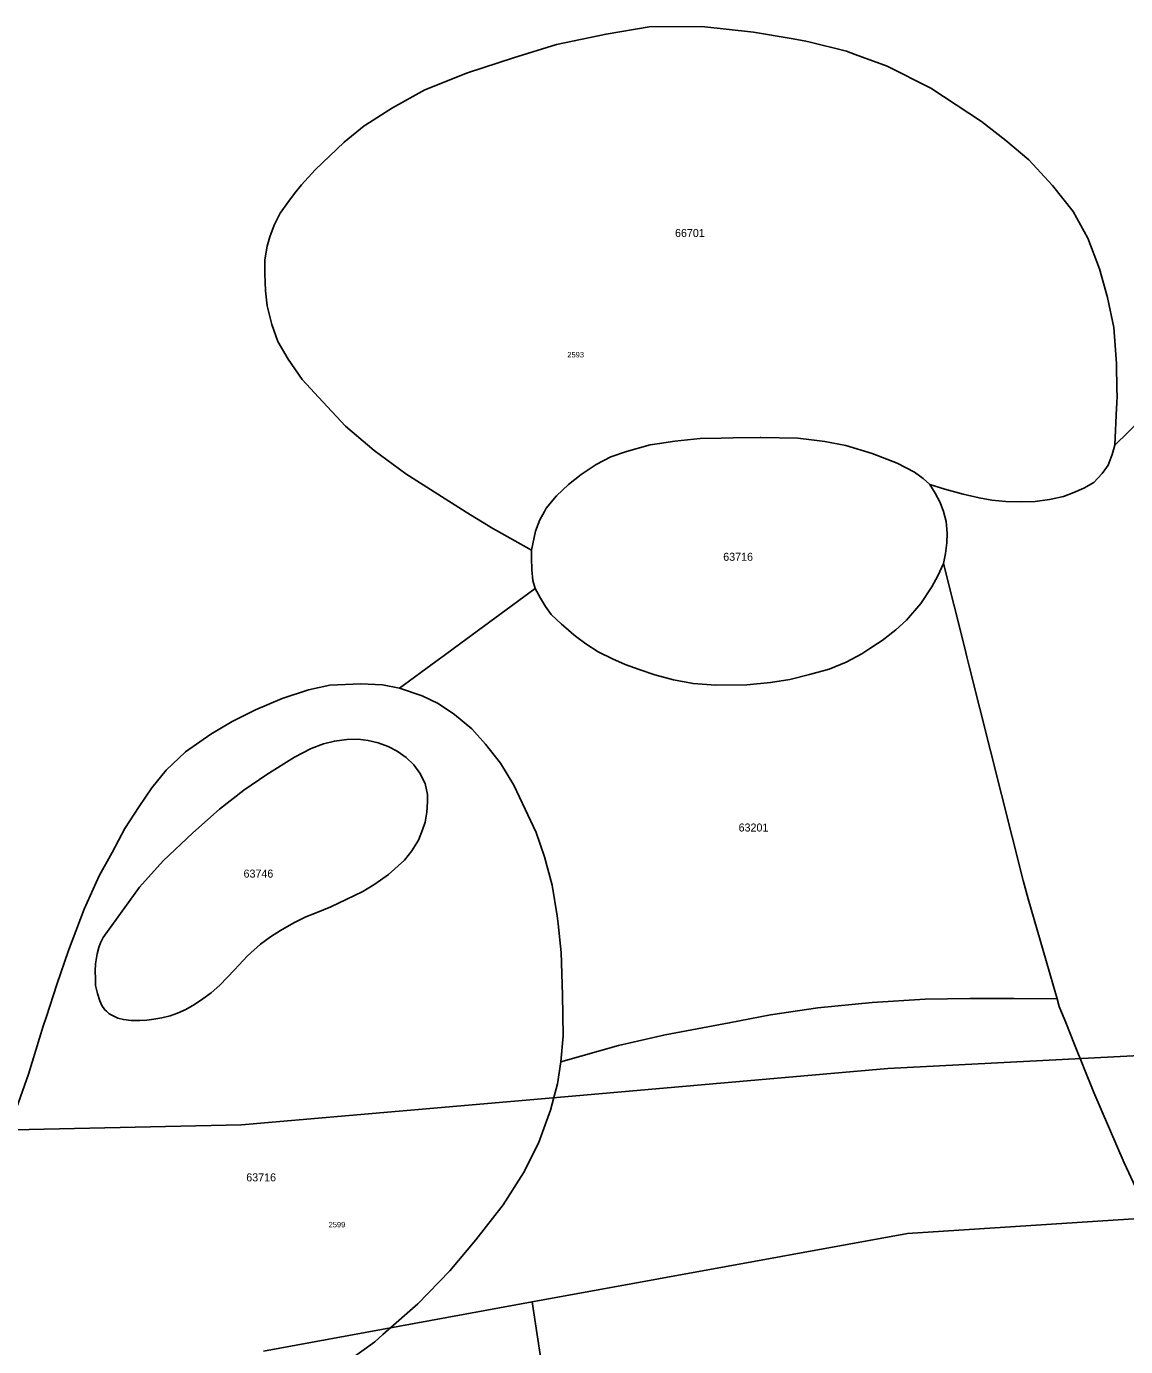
# Model space of a CAD drawing. Extents: x -546762 to -540209, y -1046851 to -1035694.
# Drawn here: x -542107.3 to -541763.8, y -1040906.5 to -1040494 of the extents above; entities that cross this region are included whole.
import ezdxf

# ---------------------------------------------------------------- set-up
doc = ezdxf.new("R2010")
doc.units = 0
for name, color, linetype in [('Vrstva 1', 7, 'Continuous'), ('Vrstva 18', 7, 'Continuous'), ('Vrstva 52', 7, 'Continuous'), ('Vrstva 53', 7, 'Continuous')]:
    doc.layers.add(name, color=color, linetype=linetype)

msp = doc.modelspace()

# ---------------------------------------------------------------- linework, layer by layer
at = {"layer": 'Vrstva 1'}
for points in [[(-541735.17, -1040814.29), (-541838.14, -1040819.65)], [(-541838.14, -1040819.65), (-541939.09, -1040828.45)], [(-541939.09, -1040828.45), (-542040.03, -1040837.25)], [(-542040.03, -1040837.25), (-542149.27, -1040839.6)], [(-541831.92, -1040871.15), (-541733.93, -1040864.83)], [(-541949.2, -1040892.56), (-541831.92, -1040871.15)], [(-542033.15, -1040907.9), (-541949.2, -1040892.56)], [(-541949.2, -1040892.56), (-541936.47, -1040977.03)]]:
    msp.add_lwpolyline(points, dxfattribs=at)
at = {"layer": 'Vrstva 52'}
for points in [[(-541766.63, -1040613.12), (-541766.57, -1040611.85), (-541766.45, -1040609.32), (-541766.48, -1040607.52), (-541766.6, -1040599.3), (-541767.49, -1040588.09), (-541769.44, -1040578.68), (-541771.98, -1040569.71), (-541775.56, -1040560.15), (-541780.19, -1040551.78), (-541786.61, -1040543.71), (-541794.08, -1040535.64), (-541801.25, -1040529.66), (-541808.87, -1040523.72), (-541824.7, -1040513.26), (-541838.29, -1040506.38), (-541848.26, -1040502.74), (-541850.99, -1040501.75), (-541862.76, -1040498.84), (-541864.28, -1040498.46), (-541868.25, -1040497.79), (-541880.12, -1040495.77), (-541896.25, -1040493.98), (-541912.68, -1040494.13), (-541926.12, -1040496.37), (-541941.66, -1040499.66), (-541955.1, -1040503.84), (-541969.44, -1040508.47), (-541982.73, -1040513.85), (-541992.89, -1040519.38), (-542001.26, -1040524.78), (-542001.7, -1040525.06), (-542007.98, -1040530.14), (-542017.09, -1040538.81), (-542021.33, -1040543.48), (-542023.55, -1040546.21), (-542025.6, -1040549.03), (-542027.99, -1040552.36), (-542029.86, -1040556.04), (-542031.23, -1040559.71), (-542032, -1040562.7), (-542032.77, -1040566.88), (-542032.77, -1040571.24), (-542032.59, -1040576.62), (-542032, -1040581.31), (-542030.55, -1040587.12), (-542028.75, -1040592.42), (-542025.43, -1040597.97), (-542021.09, -1040604.36), (-542014.69, -1040611.28), (-542007.52, -1040618.88), (-541998.65, -1040626.48), (-541988.74, -1040633.74), (-541969.91, -1040645.79), (-541961.55, -1040650.87), (-541960.42, -1040651.5), (-541955.36, -1040654.31), (-541949.45, -1040657.6)], [(-541767.2, -1040624.86), (-541754.75, -1040612.75), (-541753.86, -1040611.88), (-541752.24, -1040610.48), (-541746.99, -1040605.91), (-541745.94, -1040605), (-541736.83, -1040599.02), (-541728.16, -1040592.75)], [(-541767.2, -1040624.86), (-541766.63, -1040613.12)], [(-541949.45, -1040657.6), (-541948.24, -1040651.73), (-541947.9, -1040650.84), (-541946.87, -1040648.14), (-541945.41, -1040645.51), (-541944.83, -1040644.47), (-541941.67, -1040640.62), (-541937.91, -1040637.12), (-541933.9, -1040634.05), (-541929.21, -1040630.89), (-541924.68, -1040628.5), (-541919.73, -1040626.79), (-541912.31, -1040624.74), (-541909.49, -1040624.3), (-541904.62, -1040623.54), (-541896.69, -1040622.78), (-541890.2, -1040622.62), (-541886.44, -1040622.52), (-541878, -1040622.43), (-541877.82, -1040622.43), (-541866.21, -1040622.69), (-541861.9, -1040623.21), (-541857.76, -1040623.71), (-541851.19, -1040624.91), (-541843, -1040627.39), (-541835.15, -1040630.46), (-541829.78, -1040633.27), (-541827.05, -1040635.27), (-541825, -1040637.13)], [(-541825, -1040637.13), (-541820.27, -1040638.56), (-541814.55, -1040640.18), (-541809.6, -1040641.29), (-541805.59, -1040641.98), (-541801.24, -1040642.4), (-541796.46, -1040642.58), (-541792.1, -1040642.4), (-541787.57, -1040641.79), (-541787.07, -1040641.72), (-541783.23, -1040640.87), (-541779.98, -1040639.67), (-541776.83, -1040638.31), (-541773.75, -1040636.51), (-541771.11, -1040633.69), (-541769.77, -1040631.81), (-541769.23, -1040631.05), (-541768.03, -1040627.8), (-541767.2, -1040624.86)], [(-541820.72, -1040661.8), (-541820.04, -1040658.72), (-541819.65, -1040655.4), (-541819.5, -1040652.28), (-541819.88, -1040648.65), (-541820.71, -1040645.52), (-541821.73, -1040642.74), (-541823.25, -1040639.81), (-541825, -1040637.13)], [(-541948.34, -1040669.66), (-541948.98, -1040667.13), (-541949.37, -1040663.81), (-541949.46, -1040660), (-541949.45, -1040657.6)], [(-541882.19, -1040699.74), (-541874.76, -1040698.97), (-541868.7, -1040698.03), (-541862.56, -1040696.49), (-541856.41, -1040694.87), (-541851.12, -1040692.65), (-541846.25, -1040690), (-541843.68, -1040688.32), (-541841.37, -1040686.81), (-541839.85, -1040685.82), (-541835.58, -1040682.57), (-541832.26, -1040679.5), (-541827.82, -1040674.29), (-541824.38, -1040669.07), (-541822.43, -1040665.65), (-541820.72, -1040661.8)], [(-541812.67, -1040693.87), (-541813.38, -1040691.02), (-541814.07, -1040688.27), (-541820.72, -1040661.8)], [(-541990.68, -1040700.75), (-541979.31, -1040692.4), (-541976.74, -1040690.51), (-541973.51, -1040688.14), (-541948.34, -1040669.66)], [(-541948.34, -1040669.66), (-541946.68, -1040672.59), (-541945.07, -1040675.23), (-541943.26, -1040677.73), (-541940.1, -1040680.8), (-541938.76, -1040681.94), (-541937.02, -1040683.41), (-541936.17, -1040684.13), (-541935.28, -1040684.8), (-541932.42, -1040686.95), (-541928.66, -1040689.43), (-541924.14, -1040691.65), (-541920.21, -1040693.36), (-541915.77, -1040694.98), (-541910.91, -1040696.6), (-541905.11, -1040698.14), (-541898.96, -1040699.33), (-541891.88, -1040699.85), (-541882.19, -1040699.74)], [(-541785.2, -1040797.87), (-541788.65, -1040786), (-541794.22, -1040766.55), (-541795.85, -1040760.86), (-541795.95, -1040760.45), (-541812.67, -1040693.87)], [(-542112.75, -1040838.77), (-542106.62, -1040821.43), (-542101.99, -1040806.34), (-542101.04, -1040803.4), (-542097.81, -1040793.33), (-542094.08, -1040782.72), (-542089.18, -1040769.87), (-542084.55, -1040759.41), (-542080.52, -1040752.09), (-542076.49, -1040744.61), (-542072.01, -1040737.74), (-542068.12, -1040731.91), (-542063.64, -1040726.38), (-542057.52, -1040720.7), (-542049.6, -1040715.17), (-542043.03, -1040711.14), (-542035.71, -1040707.55), (-542027.35, -1040703.96), (-542019.13, -1040701.27), (-542012.41, -1040699.78), (-542002.77, -1040699.4), (-541996.05, -1040699.7), (-541990.68, -1040700.75)], [(-541968.12, -1040713.45), (-541973.5, -1040708.97), (-541978.58, -1040705.53), (-541983.65, -1040703.14), (-541990.68, -1040700.75)], [(-541940.24, -1040817.54), (-541939.59, -1040809.4), (-541939.74, -1040796.55), (-541940.19, -1040783.4), (-541941.12, -1040774.42), (-541941.38, -1040771.89), (-541943.03, -1040762.32), (-541945.42, -1040753.51), (-541947.96, -1040745.88), (-541951.39, -1040738.56), (-541954.98, -1040731.09), (-541959.16, -1040724.21), (-541963.79, -1040718.24), (-541968.12, -1040713.45)], [(-542071.87, -1040804.56), (-542069.67, -1040804.47), (-542067.43, -1040804.17), (-542064.99, -1040803.73), (-542062.36, -1040803.2), (-542060.07, -1040802.37), (-542057.48, -1040801.15), (-542054.7, -1040799.59), (-542052.11, -1040797.83), (-542049.58, -1040795.93), (-542046.79, -1040793.52), (-542042.26, -1040788.82), (-542038.17, -1040784.38), (-542034.15, -1040780.79), (-542031, -1040778.49), (-542027.84, -1040776.44), (-542023.66, -1040774.05), (-542019.99, -1040772.25), (-542016.7, -1040770.97), (-542012.18, -1040769.09), (-542007.31, -1040766.79), (-542002.19, -1040764.31), (-541998.35, -1040762.01), (-541994.17, -1040759.02), (-541989.14, -1040754.51), (-541986.8, -1040751.58), (-541984.8, -1040748.24), (-541983.52, -1040744.99), (-541982.67, -1040742.6), (-541982.16, -1040739.53), (-541981.9, -1040736.28), (-541981.9, -1040733.97), (-541982.67, -1040730.56), (-541984.29, -1040727.31), (-541986.17, -1040724.75), (-541988.65, -1040722.45), (-541991.46, -1040720.48), (-541994.28, -1040718.94), (-541997.35, -1040717.83), (-542000.51, -1040717.07), (-542003.58, -1040716.72), (-542007.17, -1040716.81), (-542011.01, -1040717.32), (-542014.42, -1040718.18), (-542018.26, -1040719.63), (-542023.49, -1040722.32), (-542032.15, -1040727.7), (-542039.32, -1040732.63), (-542046.94, -1040738.61), (-542055.31, -1040745.93), (-542064.57, -1040754.75), (-542071.89, -1040762.97), (-542083.24, -1040778.66), (-542084.08, -1040780.33), (-542084.62, -1040781.85), (-542085.16, -1040783.8), (-542085.64, -1040786.87), (-542085.74, -1040789.21), (-542085.69, -1040791.56), (-542085.64, -1040793.7), (-542085.06, -1040796.19), (-542084.35, -1040798.51), (-542083.67, -1040799.93), (-542082.74, -1040801.29), (-542082.25, -1040801.74), (-542081.43, -1040802.51), (-542079.96, -1040803.29), (-542078.75, -1040803.83), (-542076.89, -1040804.27)], [(-541785.2, -1040797.87), (-541798.61, -1040797.77), (-541812.5, -1040797.77), (-541826.39, -1040797.92), (-541842.97, -1040798.97), (-541860, -1040800.61), (-541874.79, -1040802.85), (-541887.63, -1040805.39), (-541907.65, -1040809.13), (-541922.28, -1040812.42), (-541940.24, -1040817.54)], [(-541694.03, -1040896.81), (-541707.18, -1040894.72), (-541716.14, -1040893.37), (-541724.65, -1040891.43), (-541732.72, -1040888.44), (-541738.69, -1040885.75), (-541744.67, -1040881.27), (-541749.45, -1040876.63), (-541752.74, -1040871.85), (-541755.28, -1040867.71), (-541756.43, -1040865.83), (-541764.27, -1040849.1), (-541773.68, -1040827.13), (-541779.93, -1040811.6), (-541782.3, -1040805.73), (-541784.53, -1040800.19), (-541785.2, -1040797.87)], [(-542076.89, -1040804.27), (-542074.5, -1040804.56), (-542071.87, -1040804.56)], [(-542010.55, -1040913.79), (-541998.45, -1040904.97), (-541995.92, -1040902.74), (-541985.01, -1040893.17), (-541975, -1040882.85), (-541966.82, -1040873.14), (-541958.31, -1040862.23), (-541951.89, -1040852.22), (-541947.26, -1040842.95), (-541943.93, -1040833.78), (-541943.52, -1040832.64), (-541942.43, -1040828.64), (-541941.28, -1040824.42), (-541940.24, -1040817.54)]]:
    msp.add_lwpolyline(points, dxfattribs=at)

# ---------------------------------------------------------------- texts
at = {"layer": 'Vrstva 18'}
for s, p in [('2593', (-541938.25, -1040597.41)), ('2599', (-542012.85, -1040869.24))]:
    msp.add_text(s, height=1.7, dxfattribs=at).set_placement(p)
at = {"layer": 'Vrstva 53'}
for s, p in [('66701', (-541904.6, -1040559.78)), ('63716', (-541889.53, -1040660.96)), ('63201', (-541884.72, -1040745.56)), ('63746', (-542039.42, -1040759.96)), ('63716', (-542038.57, -1040854.88))]:
    msp.add_text(s, height=2.5, dxfattribs=at).set_placement(p)

doc.saveas('drawing.dxf')
